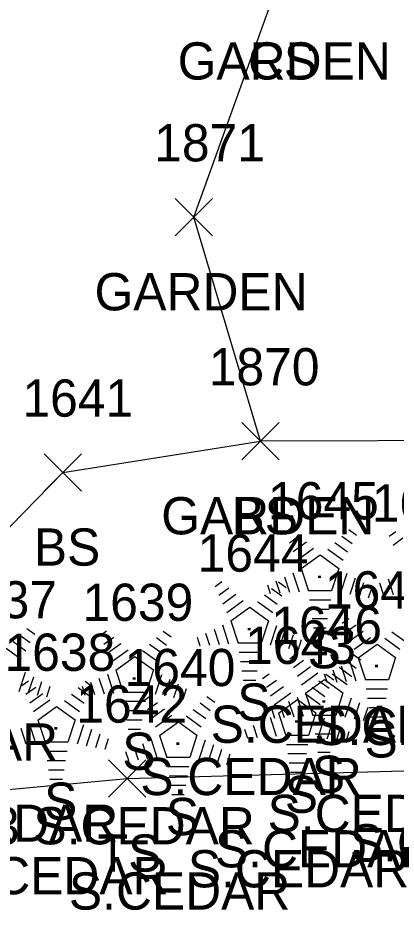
# Model space of a CAD drawing. Extents: x 1499292 to 1501024, y 534584 to 538043.
# Drawn here: x 1499935.33 to 1499955.65, y 537630.52 to 537678.44 of the extents above; entities that cross this region are included whole.
import ezdxf

# ---------------------------------------------------------------- set-up
doc = ezdxf.new("R2010")
doc.units = 0
for name, color, linetype in [('L_A', 7, 'Continuous'), ('L_C', 7, 'Continuous'), ('L_I', 7, 'Continuous'), ('L_TIC', 7, 'Continuous'), ('LAPB', 7, 'Continuous'), ('LELB', 7, 'Continuous'), ('LTC', 7, 'Continuous')]:
    doc.layers.add(name, color=color, linetype=linetype)

msp = doc.modelspace()

# ---------------------------------------------------------------- linework, layer by layer
at = {"layer": 'L_TIC'}
for points in [[(1499943.782, 537666.728), (1499945.782, 537668.728)], [(1499945.782, 537666.728), (1499943.782, 537668.728)], [(1499947.365, 537654.7), (1499949.365, 537656.7)], [(1499949.365, 537654.7), (1499947.365, 537656.7)], [(1499947.365, 537654.7), (1499949.365, 537656.7)], [(1499949.365, 537654.7), (1499947.365, 537656.7)], [(1499936.751, 537653.019), (1499938.751, 537655.019)], [(1499938.751, 537653.019), (1499936.751, 537655.019)], [(1499940.209, 537636.588), (1499942.209, 537638.588)], [(1499942.209, 537636.588), (1499940.209, 537638.588)]]:
    msp.add_lwpolyline(points, dxfattribs=at)
at = {"layer": 'LAPB'}
msp.add_lwpolyline([(1500008.149, 537662.504), (1499976.291, 537657.715), (1499960.955, 537655.744), (1499948.365, 537655.7), (1499944.782, 537667.728), (1499949.249, 537680.121), (1499961.303, 537682.861), (1499970.991, 537673.07), (1499976.904, 537664.777), (1499986.731, 537668.48), (1499987.916, 537680.302), (1499978.247, 537691.097), (1499980.645, 537701.007), (1499987.039, 537704.664), (1499995.658, 537692.472), (1500004.638, 537676.076)], dxfattribs=at)
at = {"layer": 'LELB'}
for points in [[(1499898.052, 537654.523), (1499915.347, 537646.709), (1499931.422, 537647.554), (1499937.751, 537654.019), (1499948.365, 537655.7)], [(1499898.052, 537654.523), (1499910.254, 537639.037), (1499923.982, 537635.989), (1499941.209, 537637.588), (1499959.262, 537638.094), (1499978.567, 537642.414), (1499993.025, 537642.588)]]:
    msp.add_lwpolyline(points, dxfattribs=at)
at = {"layer": 'LTC'}
for p, q in [((1499949.704, 537650.713), (1499950.059, 537650.97)), ((1499953.102, 537650.953), (1499953.522, 537650.649)), ((1499955.274, 537650.594), (1499955.629, 537650.851)), ((1499949.914, 537650.247), (1499950.443, 537650.631)), ((1499952.731, 537650.605), (1499953.281, 537650.206)), ((1499955.484, 537650.128), (1499956.013, 537650.513)), ((1499950.123, 537649.781), (1499950.827, 537650.293)), ((1499950.333, 537649.316), (1499951.211, 537649.954)), ((1499951.989, 537649.908), (1499952.799, 537649.319)), ((1499952.36, 537650.256), (1499953.039, 537649.763)), ((1499950.557, 537648.861), (1499951.569, 537649.595)), ((1499951.569, 537649.595), (1499952.566, 537648.87)), ((1499949.647, 537648.425), (1499949.919, 537647.59)), ((1499950.103, 537648.641), (1499950.434, 537647.622)), ((1499950.557, 537648.861), (1499950.944, 537647.667)), ((1499952.566, 537648.87), (1499952.175, 537647.667)), ((1499953.004, 537648.599), (1499952.666, 537647.56)), ((1499945.925, 537647.904), (1499946.28, 537648.162)), ((1499948.737, 537647.992), (1499948.889, 537647.524)), ((1499949.192, 537648.209), (1499949.404, 537647.557)), ((1499949.324, 537648.145), (1499949.743, 537647.84)), ((1499953.448, 537648.349), (1499953.161, 537647.464)), ((1499953.893, 537648.099), (1499953.656, 537647.369)), ((1499954.762, 537648.09), (1499954.974, 537647.438)), ((1499955.218, 537648.306), (1499955.489, 537647.471)), ((1499946.135, 537647.439), (1499946.664, 537647.823)), ((1499946.345, 537646.973), (1499947.048, 537647.484)), ((1499948.952, 537647.796), (1499949.502, 537647.397)), ((1499952.175, 537647.667), (1499950.944, 537647.667)), ((1499954.337, 537647.849), (1499954.15, 537647.274)), ((1499954.307, 537647.873), (1499954.459, 537647.405)), ((1499946.554, 537646.507), (1499947.432, 537647.145)), ((1499948.21, 537647.1), (1499949.02, 537646.511)), ((1499948.582, 537647.448), (1499949.261, 537646.954)), ((1499952.137, 537647.167), (1499950.992, 537647.167)), ((1499946.779, 537646.052), (1499947.79, 537646.787)), ((1499947.79, 537646.787), (1499948.787, 537646.062)), ((1499952.053, 537646.667), (1499951.064, 537646.667)), ((1499946.779, 537646.052), (1499947.166, 537644.859)), ((1499948.787, 537646.062), (1499948.396, 537644.859)), ((1499951.969, 537646.167), (1499951.137, 537646.167)), ((1499952.76, 537645.926), (1499953.115, 537646.183)), ((1499935.819, 537645.637), (1499936.238, 537645.333)), ((1499945.869, 537645.617), (1499946.14, 537644.781)), ((1499946.324, 537645.833), (1499946.655, 537644.814)), ((1499949.225, 537645.791), (1499948.887, 537644.751)), ((1499949.67, 537645.54), (1499949.382, 537644.656)), ((1499951.885, 537645.667), (1499951.21, 537645.667)), ((1499952.97, 537645.46), (1499953.499, 537645.845)), ((1499935.448, 537645.289), (1499935.997, 537644.89)), ((1499939.748, 537645.261), (1499940.103, 537645.518)), ((1499939.958, 537644.796), (1499940.487, 537645.18)), ((1499942.775, 537645.153), (1499943.325, 537644.754)), ((1499943.146, 537645.501), (1499943.566, 537645.197)), ((1499944.958, 537645.183), (1499945.11, 537644.715)), ((1499945.413, 537645.4), (1499945.625, 537644.748)), ((1499950.114, 537645.29), (1499949.877, 537644.561)), ((1499953.179, 537644.995), (1499953.883, 537645.506)), ((1499953.389, 537644.529), (1499954.267, 537645.167)), ((1499955.045, 537645.121), (1499955.855, 537644.533)), ((1499955.416, 537645.47), (1499956.095, 537644.976)), ((1499934.706, 537644.592), (1499935.515, 537644.004)), ((1499935.077, 537644.941), (1499935.756, 537644.447)), ((1499940.167, 537644.33), (1499940.871, 537644.841)), ((1499942.404, 537644.805), (1499943.083, 537644.311)), ((1499948.396, 537644.859), (1499947.166, 537644.859)), ((1499950.558, 537645.04), (1499950.372, 537644.466)), ((1499953.613, 537644.074), (1499954.625, 537644.808)), ((1499954.625, 537644.808), (1499955.622, 537644.083)), ((1499940.377, 537643.864), (1499941.255, 537644.502)), ((1499940.601, 537643.409), (1499941.613, 537644.143)), ((1499941.613, 537644.143), (1499942.61, 537643.418)), ((1499942.033, 537644.456), (1499942.843, 537643.868)), ((1499948.358, 537644.359), (1499947.213, 537644.359)), ((1499949.933, 537644.024), (1499950.288, 537644.281)), ((1499953.332, 537644.264), (1499953.751, 537643.96)), ((1499948.274, 537643.859), (1499947.286, 537643.859)), ((1499950.143, 537643.559), (1499950.672, 537643.943)), ((1499952.703, 537643.638), (1499952.975, 537642.803)), ((1499952.96, 537643.916), (1499953.51, 537643.517)), ((1499953.159, 537643.855), (1499953.49, 537642.835)), ((1499953.613, 537644.074), (1499954, 537642.88)), ((1499955.622, 537644.083), (1499955.231, 537642.88)), ((1499935.72, 537643.284), (1499935.382, 537642.244)), ((1499940.147, 537643.19), (1499940.478, 537642.171)), ((1499940.601, 537643.409), (1499940.988, 537642.216)), ((1499942.61, 537643.418), (1499942.219, 537642.216)), ((1499943.048, 537643.148), (1499942.71, 537642.108)), ((1499948.19, 537643.359), (1499947.359, 537643.359)), ((1499948.479, 537642.951), (1499948.834, 537643.208)), ((1499950.352, 537643.093), (1499951.056, 537643.604)), ((1499950.562, 537642.627), (1499951.44, 537643.265)), ((1499951.793, 537643.205), (1499951.945, 537642.737)), ((1499951.877, 537643.191), (1499952.296, 537642.887)), ((1499952.218, 537643.219), (1499953.028, 537642.631)), ((1499952.248, 537643.422), (1499952.46, 537642.77)), ((1499952.59, 537643.568), (1499953.269, 537643.074)), ((1499935.551, 537642.58), (1499935.906, 537642.837)), ((1499936.165, 537643.033), (1499935.877, 537642.149)), ((1499936.61, 537642.783), (1499936.372, 537642.054)), ((1499938.949, 537642.82), (1499939.369, 537642.515)), ((1499939.236, 537642.757), (1499939.448, 537642.105)), ((1499939.691, 537642.973), (1499939.963, 537642.138)), ((1499943.492, 537642.897), (1499943.205, 537642.013)), ((1499948.107, 537642.859), (1499947.432, 537642.859)), ((1499948.689, 537642.486), (1499949.218, 537642.87)), ((1499950.787, 537642.172), (1499951.798, 537642.906)), ((1499951.506, 537642.843), (1499952.056, 537642.444)), ((1499951.798, 537642.906), (1499952.795, 537642.181)), ((1499955.231, 537642.88), (1499954, 537642.88)), ((1499935.761, 537642.114), (1499936.29, 537642.498)), ((1499937.054, 537642.533), (1499936.867, 537641.959)), ((1499938.578, 537642.472), (1499939.128, 537642.073)), ((1499938.781, 537642.54), (1499938.933, 537642.072)), ((1499942.219, 537642.216), (1499940.988, 537642.216)), ((1499943.937, 537642.647), (1499943.7, 537641.918)), ((1499944.381, 537642.397), (1499944.194, 537641.823)), ((1499948.898, 537642.02), (1499949.602, 537642.531)), ((1499949.108, 537641.554), (1499949.986, 537642.192)), ((1499951.135, 537642.495), (1499951.814, 537642.001)), ((1499952.795, 537642.181), (1499952.404, 537640.979)), ((1499955.193, 537642.38), (1499954.048, 537642.38)), ((1499935.97, 537641.648), (1499936.674, 537642.16)), ((1499936.18, 537641.183), (1499937.058, 537641.82)), ((1499937.836, 537641.775), (1499938.646, 537641.186)), ((1499938.207, 537642.123), (1499938.887, 537641.63)), ((1499942.181, 537641.716), (1499941.036, 537641.716)), ((1499942.09, 537641.757), (1499942.445, 537642.014)), ((1499945.488, 537641.997), (1499945.908, 537641.693)), ((1499949.332, 537641.099), (1499950.344, 537641.833)), ((1499949.877, 537641.736), (1499950.148, 537640.901)), ((1499950.332, 537641.953), (1499950.663, 537640.934)), ((1499950.344, 537641.833), (1499951.341, 537641.108)), ((1499950.764, 537642.146), (1499951.574, 537641.558)), ((1499950.787, 537642.172), (1499951.174, 537640.979)), ((1499953.233, 537641.911), (1499952.895, 537640.871)), ((1499955.109, 537641.88), (1499954.12, 537641.88)), ((1499936.404, 537640.728), (1499937.416, 537641.462)), ((1499937.416, 537641.462), (1499938.413, 537640.737)), ((1499942.3, 537641.291), (1499942.829, 537641.675)), ((1499942.509, 537640.825), (1499943.213, 537641.337)), ((1499944.746, 537641.3), (1499945.426, 537640.807)), ((1499945.117, 537641.649), (1499945.667, 537641.25)), ((1499948.966, 537641.303), (1499949.118, 537640.835)), ((1499949.421, 537641.52), (1499949.633, 537640.868)), ((1499953.677, 537641.66), (1499953.39, 537640.776)), ((1499954.122, 537641.41), (1499953.885, 537640.681)), ((1499955.025, 537641.38), (1499954.193, 537641.38)), ((1499942.097, 537641.216), (1499941.108, 537641.216)), ((1499942.719, 537640.36), (1499943.597, 537640.998)), ((1499944.375, 537640.952), (1499945.185, 537640.363)), ((1499948.878, 537640.88), (1499949.209, 537639.861)), ((1499949.332, 537641.099), (1499949.719, 537639.906)), ((1499951.341, 537641.108), (1499950.95, 537639.906)), ((1499952.404, 537640.979), (1499951.174, 537640.979)), ((1499951.779, 537640.838), (1499951.441, 537639.798)), ((1499954.941, 537640.88), (1499954.266, 537640.88)), ((1499954.566, 537641.16), (1499954.38, 537640.586)), ((1499935.494, 537640.292), (1499935.766, 537639.457)), ((1499935.95, 537640.508), (1499936.281, 537639.489)), ((1499936.404, 537640.728), (1499936.792, 537639.534)), ((1499938.413, 537640.737), (1499938.022, 537639.534)), ((1499938.851, 537640.466), (1499938.513, 537639.427)), ((1499942.013, 537640.716), (1499941.181, 537640.716)), ((1499942.943, 537639.905), (1499943.955, 537640.639)), ((1499943.955, 537640.639), (1499944.952, 537639.914)), ((1499947.967, 537640.447), (1499948.179, 537639.795)), ((1499948.422, 537640.663), (1499948.694, 537639.828)), ((1499952.366, 537640.479), (1499951.221, 537640.479)), ((1499952.223, 537640.587), (1499951.936, 537639.703)), ((1499952.668, 537640.337), (1499952.431, 537639.608)), ((1499939.295, 537640.216), (1499939.008, 537639.331)), ((1499939.74, 537639.966), (1499939.503, 537639.236)), ((1499941.929, 537640.216), (1499941.254, 537640.216)), ((1499942.943, 537639.905), (1499943.331, 537638.711)), ((1499944.952, 537639.914), (1499944.561, 537638.711)), ((1499947.511, 537640.23), (1499947.664, 537639.762)), ((1499950.95, 537639.906), (1499949.719, 537639.906)), ((1499952.282, 537639.979), (1499951.294, 537639.979)), ((1499953.112, 537640.087), (1499952.925, 537639.513)), ((1499938.022, 537639.534), (1499936.792, 537639.534)), ((1499940.184, 537639.715), (1499939.997, 537639.141)), ((1499942.033, 537639.469), (1499942.305, 537638.634)), ((1499942.489, 537639.685), (1499942.82, 537638.666)), ((1499945.39, 537639.643), (1499945.052, 537638.604)), ((1499945.834, 537639.393), (1499945.547, 537638.508)), ((1499950.911, 537639.406), (1499949.767, 537639.406)), ((1499952.198, 537639.479), (1499951.367, 537639.479)), ((1499937.984, 537639.034), (1499936.839, 537639.034)), ((1499941.123, 537639.036), (1499941.275, 537638.568)), ((1499941.578, 537639.253), (1499941.79, 537638.601)), ((1499946.279, 537639.143), (1499946.042, 537638.413)), ((1499946.723, 537638.893), (1499946.536, 537638.318)), ((1499950.828, 537638.906), (1499949.839, 537638.906)), ((1499952.115, 537638.979), (1499951.44, 537638.979)), ((1499937.9, 537638.534), (1499936.912, 537638.534)), ((1499944.561, 537638.711), (1499943.331, 537638.711)), ((1499950.744, 537638.406), (1499949.912, 537638.406)), ((1499937.816, 537638.034), (1499936.984, 537638.034)), ((1499944.523, 537638.211), (1499943.378, 537638.211)), ((1499950.66, 537637.906), (1499949.985, 537637.906)), ((1499937.732, 537637.534), (1499937.057, 537637.534)), ((1499944.439, 537637.711), (1499943.451, 537637.711)), ((1499944.355, 537637.211), (1499943.523, 537637.211)), ((1499944.271, 537636.711), (1499943.596, 537636.711))]:
    msp.add_line(p, q, dxfattribs=at)

# ---------------------------------------------------------------- texts
at = {"layer": 'L_A'}
for s, p in [('GARDEN', (1499943.918, 537675.121)), ('CS', (1499947.69, 537675.121)), ('GARDEN', (1499939.452, 537662.728)), ('GARDEN', (1499943.034, 537650.7)), ('BS', (1499946.806, 537650.7)), ('BS', (1499936.192, 537649.019)), ('S', (1499950.895, 537643.505)), ('S', (1499947.116, 537640.696)), ('S', (1499953.951, 537638.718)), ('S', (1499940.939, 537638.053)), ('S', (1499951.124, 537636.816)), ('S', (1499936.742, 537635.371)), ('S', (1499949.67, 537635.743)), ('S', (1499943.281, 537634.549)), ('TS', (1499939.619, 537632.588))]:
    msp.add_text(s, height=2, dxfattribs=at).set_placement(p)
at = {"layer": 'L_C'}
for s, p in [('S.CEDAR', (1499945.69, 537639.505)), ('S.CEDAR', (1499951.26, 537639.386)), ('S.CEDAR', (1499925.603, 537638.554)), ('S.CEDAR', (1499941.911, 537636.696)), ('S.CEDAR', (1499948.746, 537634.718)), ('3 S.CEDAR', (1499926.611, 537634.189)), ('3 S.CEDAR', (1499933.939, 537634.053)), ('S.CEDAR', (1499953.163, 537633.135)), ('S.CEDAR', (1499945.919, 537632.816)), ('S.CEDAR', (1499944.465, 537631.743)), ('S.CEDAR', (1499931.537, 537631.371)), ('S.CEDAR', (1499938.076, 537630.549))]:
    msp.add_text(s, height=2, dxfattribs=at).set_placement(p)
at = {"layer": 'L_I'}
for s, p in [('1871', (1499942.656, 537670.728)), ('1870', (1499945.585, 537658.7)), ('1870', (1499945.585, 537658.7)), ('1641', (1499935.578, 537657.019)), ('1645', (1499948.769, 537651.505)), ('1648', (1499954.339, 537651.386)), ('1644', (1499944.99, 537648.696)), ('1647', (1499951.825, 537646.718)), ('1637', (1499931.485, 537646.189)), ('1639', (1499938.805, 537646.053)), ('1646', (1499948.943, 537644.816)), ('1643', (1499947.544, 537643.743)), ('1638', (1499934.616, 537643.371)), ('1640', (1499941.068, 537642.549)), ('1642', (1499938.469, 537640.588))]:
    msp.add_text(s, height=2, dxfattribs=at).set_placement(p)
at = {"layer": 'LTC'}
for p in [(1499951.452, 537648.609), (1499947.673, 537645.8), (1499954.508, 537643.822), (1499941.496, 537643.157), (1499951.681, 537641.92), (1499937.299, 537640.475), (1499950.226, 537640.847), (1499943.838, 537639.653)]:
    msp.add_text('.', height=1.037, rotation=270, dxfattribs=at).set_placement(p)

doc.saveas('drawing.dxf')
